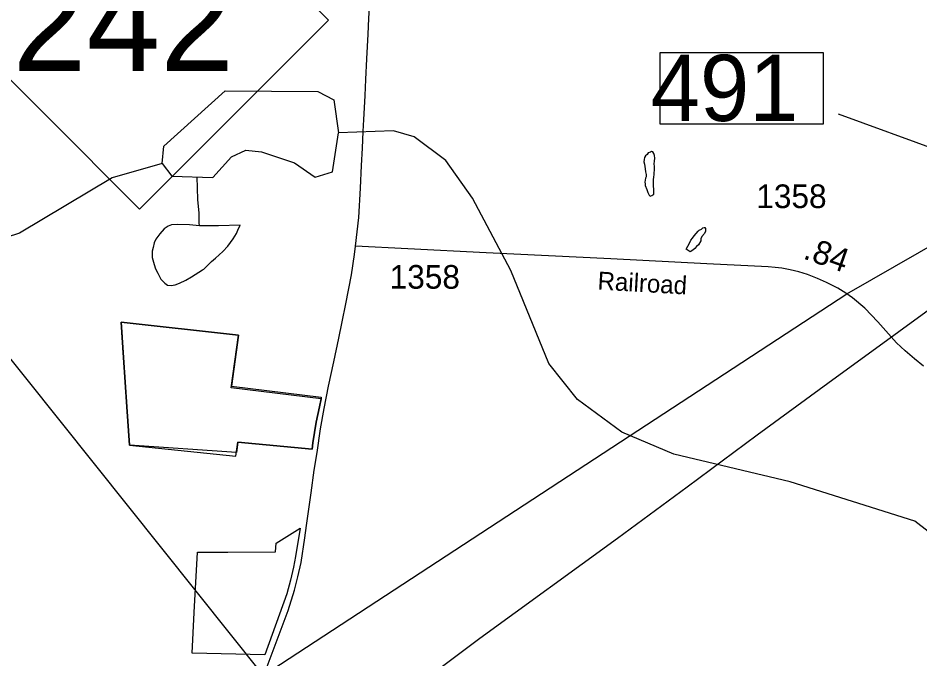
# Model space of a CAD drawing. Extents: x 2082433 to 2279600, y 546599 to 755198.
# Drawn here: x 2135079 to 2139852, y 600726 to 604115 of the extents above; entities that cross this region are included whole.
import ezdxf

# ---------------------------------------------------------------- set-up
doc = ezdxf.new("R2010")
doc.units = 0
for name, color, linetype in [('Exist Boundary Political City Limit New', 7, 'Continuous'), ('Exist Boundary Political Fire Districts', 7, 'Continuous'), ('Exist Hydrographic Misc Water Feature', 7, 'Continuous'), ('Exist Hydrographic Pond Under 1500 Sq Ft', 7, 'Continuous'), ('Exist Road Primary Interstate Structure Standard Bridge Number Label', 7, 'Continuous'), ('Exist Road Primary NC Attributed', 7, 'Continuous'), ('Exist Road Primary NC Shield CELL', 7, 'Continuous'), ('Exist Road Primary NC Shield Number Label', 7, 'Continuous'), ('Exist Road Secondary Mileage Hundredths English Label', 7, 'Continuous'), ('Exist Road Secondary Type 51 Attributed', 7, 'Continuous'), ('Exist Road Secondary Type 51 Label', 7, 'Continuous'), ('Exist Road Secondary Type 51 Number Label', 7, 'Continuous'), ('Exist Utilities Electrical Transmission Line', 7, 'Continuous'), ('Map Preparation Boundary City Limit Buffer Line', 7, 'Continuous')]:
    doc.layers.add(name, color=color, linetype=linetype)

msp = doc.modelspace()

# ---------------------------------------------------------------- linework, layer by layer
at = {"layer": 'Exist Boundary Political City Limit New'}
for points in [[(2136656.5, 601978.1), (2136639.5, 601868.3), (2136635, 601835.1), (2136242.8, 601872.6), (2136234.8, 601817.2), (2135669.8, 601856.6), (2135655.8, 602058.8), (2135637.5, 602320.6), (2135635.8, 602344.6), (2135624.5, 602506.8), (2136245.8, 602438.5), (2136208.8, 602168.7), (2136684.2, 602110.8), (2136682.5, 602101.9), (2136673.8, 602058.5), (2136656.5, 601978.1)], [(2136502.5, 601071.1), (2136385, 600748.5), (2136000, 600756.9), (2136012, 600970.8), (2136028.8, 601290.8), (2136036, 601290.8), (2136188.8, 601291.4), (2136442.5, 601292.2), (2136445.8, 601338.6), (2136573, 601417.9), (2136548, 601268.2), (2136536.8, 601211.1), (2136520.8, 601142.6), (2136502.5, 601071.1)]]:
    msp.add_lwpolyline(points, dxfattribs=at)
at = {"layer": 'Exist Boundary Political Fire Districts'}
for points in [[(2125185.8, 609236.3), (2127409.2, 608956.3), (2130289.8, 608255.9), (2136376.8, 600637.7), (2139465.5, 602656.7), (2141242.8, 603675.4), (2141795.1, 603915), (2144979.3, 603672.9), (2148226.1, 607636.4), (2150227.4, 608573.5)], [(2135669.7, 601856.6), (2136232, 601798.8), (2136242.7, 601872.6), (2136634.9, 601835), (2136639.4, 601868.3), (2136656.4, 601978.1), (2136673.7, 602058.5), (2136682.5, 602101.9), (2136207.6, 602159.7), (2136245.7, 602438.5), (2135624.4, 602506.7), (2135637.5, 602320.6), (2135655.8, 602058.8), (2135669.7, 601856.6)]]:
    msp.add_lwpolyline(points, dxfattribs=at)
at = {"layer": 'Exist Hydrographic Misc Water Feature'}
for points in [[(2140618.9, 600976.4), (2140058.9, 601273.1), (2139824.9, 601455.1), (2139165.9, 601661.9), (2138548.8, 601808.9), (2138273.9, 601926), (2138039.7, 602098.1), (2137888.8, 602288.1), (2137686.8, 602781), (2137484.8, 603162.3), (2137342.7, 603362), (2137175.8, 603486.7), (2137066.7, 603518.5), (2136775.7, 603508)], [(2135842.7, 603346.4), (2135576.8, 603269.9), (2135086.7, 602978), (2134878.8, 602910), (2134561.8, 602906.5), (2134136.7, 602980.7), (2133911.7, 602945.9), (2133803.7, 602912.1), (2133588.6, 602562.1), (2133447.7, 602496), (2133222.5, 602467.8), (2133089.7, 602509.9), (2132829.7, 602718.6), (2132636.7, 603089.9), (2132535.6, 603308.5), (2132318.7, 603473.6)], [(2138446.3, 603312.2), (2138448, 603330.2), (2138445.7, 603344), (2138447.6, 603358.3), (2138449.8, 603374.1), (2138448, 603388.2), (2138444.1, 603398.1), (2138437.5, 603408), (2138431.6, 603410.1), (2138425.8, 603406.2), (2138413.5, 603401.9), (2138407.6, 603393.9), (2138399.8, 603385.7), (2138393.9, 603377.8), (2138391.8, 603367.9), (2138391.6, 603354.1), (2138393.9, 603342), (2138398.4, 603317.8), (2138400, 603302.2), (2138402.3, 603288), (2138402.5, 603275.8), (2138400.2, 603268.1), (2138398.6, 603257.8), (2138396.5, 603248), (2138398.2, 603238), (2138398.6, 603229.8), (2138406.4, 603207.9), (2138412.7, 603192), (2138418.9, 603178.1), (2138425, 603173.9), (2138432.6, 603176), (2138438.8, 603180.3), (2138442.9, 603184.2), (2138444.5, 603202.2), (2138442.2, 603234.2), (2138442.5, 603248.3), (2138442.2, 603262.2), (2138444.1, 603274), (2138446.1, 603288.3), (2138446.1, 603294), (2138446.3, 603312.2)], [(2136039.9, 603015.6), (2136038, 603031.7), (2136038, 603055.6), (2136037.6, 603083.6), (2136031.4, 603155.5), (2136027.1, 603275.4)], [(2136039.9, 603015.6), (2135985.9, 603021.3), (2135922.2, 603023.2), (2135892, 603020.9), (2135874.4, 603015), (2135852.2, 603001), (2135830.3, 602974.7), (2135808.8, 602946.7), (2135800.6, 602926.4), (2135795, 602902.5), (2135789.1, 602882.3), (2135788.9, 602848.7), (2135799.1, 602812.7), (2135807.5, 602788.7), (2135819, 602766.7), (2135827.2, 602748.9), (2135835.4, 602735), (2135855.5, 602712.9), (2135869.7, 602703.1), (2135889.8, 602700.9), (2135911.7, 602705.2), (2135933.4, 602713.3), (2135967.5, 602729.2), (2135997.4, 602747.4), (2136054.8, 602783.8), (2136063.2, 602787.8), (2136087.2, 602812.1), (2136103, 602828), (2136124.7, 602846.2), (2136162.7, 602880.2), (2136190.4, 602908.4), (2136218.3, 602948.4), (2136236.1, 602976.6), (2136242.2, 602992.7), (2136254.1, 603020.4), (2136140.3, 603016.2), (2136058.1, 603015.6), (2136039.9, 603015.6)], [(2138691.6, 602937.3), (2138679.9, 602915.2), (2138670.1, 602907.3), (2138659.8, 602897.1), (2138649.6, 602887.3), (2138636, 602879.2), (2138626, 602885.2), (2138614.1, 602893.1), (2138631.7, 602925.3), (2138639.5, 602941.1), (2138647.5, 602951.2), (2138657.6, 602963.1), (2138667.8, 602975.4), (2138677.4, 602987.3), (2138683.4, 602993.3), (2138695.1, 602999.2), (2138703.3, 603005.3), (2138709.2, 603007.6), (2138713.5, 603007.4), (2138717.6, 603001.5), (2138717.4, 602987.3), (2138711.5, 602975.2), (2138697.3, 602959.5), (2138691.6, 602947.4), (2138691.6, 602937.3)]]:
    msp.add_lwpolyline(points, dxfattribs=at)
at = {"layer": 'Exist Hydrographic Pond Under 1500 Sq Ft'}
for points in [[(2135842.7, 603346.4), (2135850.7, 603438.1), (2136174.7, 603730.1), (2136665.8, 603726.7), (2136749.7, 603682.4), (2136775.7, 603508)], [(2136284.8, 603416.2), (2136367.7, 603408), (2136542.8, 603348.7), (2136651.7, 603274.3), (2136742.7, 603302), (2136775.7, 603508)], [(2135842.7, 603346.4), (2135892.8, 603279.8), (2136109.7, 603272.2), (2136209.8, 603381.7), (2136284.8, 603416.2)]]:
    msp.add_lwpolyline(points, dxfattribs=at)
at = {"layer": 'Exist Road Primary Interstate Structure Standard Bridge Number Label'}
msp.add_line((2141689.2, 602780.9), (2139421.4, 603606.5), dxfattribs=at)
msp.add_lwpolyline([(2139341.5, 603930.6), (2138475, 603930.6), (2138475, 603555), (2139341.5, 603555)], close=True, dxfattribs=at)
at = {"layer": 'Exist Road Primary NC Attributed'}
for points in [[(2136865.7, 602908), (2136882.2, 603060.7), (2136892.2, 603214.9), (2136897.5, 603335.6), (2136902.5, 603426.7), (2136906.2, 603515.6), (2136909, 603578.2), (2136910.3, 603609.2), (2136915.6, 603705.3), (2136920.6, 603789.5), (2136925.8, 603899.8), (2136932.1, 604030.3), (2136936.1, 604113.5), (2136942.3, 604235.4)], [(2136387.6, 600658.5), (2136508.9, 600982.1), (2136542.5, 601089.1), (2136559.9, 601160.1), (2136577.5, 601236.8), (2136597.1, 601367.2), (2136606.4, 601432.4), (2136630.1, 601605), (2136645.6, 601724.1), (2136661.8, 601818), (2136680.4, 601942.3), (2136699.7, 602049.9), (2136722.7, 602169.3), (2136750.1, 602297.1), (2136776.5, 602423), (2136794.9, 602508.2), (2136814.1, 602603.3), (2136843.7, 602757.8), (2136860.2, 602865.3), (2136865.7, 602908)]]:
    msp.add_lwpolyline(points, dxfattribs=at)
at = {"layer": 'Exist Road Primary NC Shield CELL'}
msp.add_lwpolyline([(2134723.7, 604103.5), (2135722.6, 605102.5), (2136721.6, 604103.5), (2135722.6, 603104.5)], close=True, dxfattribs=at)
at = {"layer": 'Exist Road Secondary Type 51 Attributed'}
msp.add_lwpolyline([(2139871, 602274.6), (2139822.4, 602312.3), (2139773.8, 602354.6), (2139728.1, 602398.1), (2139629.5, 602508.4), (2139560.2, 602581.8), (2139495.5, 602635.7), (2139459.3, 602661.1), (2139416.7, 602687.1), (2139358.1, 602717), (2139310.5, 602737.8), (2139256.1, 602758.9), (2139210.6, 602772.7), (2139164.5, 602784), (2139121.7, 602791.6), (2139085.7, 602796.4), (2139048.8, 602799.8), (2138724.8, 602815.8), (2138216.9, 602841.9), (2137556.8, 602873), (2137141.1, 602895.3), (2136865.7, 602908)], dxfattribs=at)
at = {"layer": 'Exist Utilities Electrical Transmission Line'}
msp.add_lwpolyline([(2135510.3, 599346), (2136050.3, 599742.2), (2136793.7, 600289.3), (2137523.2, 600836.5), (2138250.6, 601365.5), (2138619.3, 601637), (2138990, 601910.6), (2139364.7, 602184), (2139739.4, 602457.6), (2140486.9, 603000.7), (2140829.8, 603250.2), (2141575.1, 603803.2), (2141969.6, 604095), (2142338.3, 604368.5), (2142712.9, 604640), (2143476.4, 605209.1), (2143859, 605478.7), (2144235.8, 605746.2), (2144606.6, 606003.9), (2144985.1, 606269.4), (2145363.9, 606534.9), (2145742.6, 606790.6), (2146119.5, 607050.1), (2146496.2, 607313.6)], dxfattribs=at)
at = {"layer": 'Map Preparation Boundary City Limit Buffer Line'}
for points in [[(2136656.5, 601978.1), (2136639.5, 601868.3), (2136635, 601835.1), (2136242.8, 601872.6), (2136234.8, 601817.2), (2135669.8, 601856.6), (2135655.8, 602058.8), (2135637.5, 602320.6), (2135635.8, 602344.6), (2135624.5, 602506.8), (2136245.8, 602438.5), (2136208.8, 602168.7), (2136684.2, 602110.8), (2136682.5, 602101.9), (2136673.8, 602058.5), (2136656.5, 601978.1)], [(2136502.5, 601071.1), (2136385, 600748.5), (2136000, 600756.9), (2136012, 600970.8), (2136028.8, 601290.8), (2136036, 601290.8), (2136188.8, 601291.4), (2136442.5, 601292.2), (2136445.8, 601338.6), (2136573, 601417.9), (2136548, 601268.2), (2136536.8, 601211.1), (2136520.8, 601142.6), (2136502.5, 601071.1)]]:
    msp.add_lwpolyline(points, dxfattribs=at)

# ---------------------------------------------------------------- texts
at = {"layer": 'Exist Road Primary Interstate Structure Standard Bridge Number Label'}
msp.add_text('491', height=350, dxfattribs=at).set_placement((2138427.6, 603570.6))
at = {"layer": 'Exist Road Primary NC Shield Number Label'}
msp.add_text('242', height=525, dxfattribs=at).set_placement((2135051, 603834.3))
at = {"layer": 'Exist Road Secondary Mileage Hundredths English Label'}
msp.add_text('.84', height=125, rotation=340.71, dxfattribs=at).set_placement((2139228.6, 602844.7))
at = {"layer": 'Exist Road Secondary Type 51 Label'}
msp.add_text('Railroad', height=95, rotation=356.7894, dxfattribs=at).set_placement((2138144.2, 602679.8))
at = {"layer": 'Exist Road Secondary Type 51 Number Label'}
for p in [(2138985.9, 603110.2), (2137045.9, 602683.9)]:
    msp.add_text('1358', height=125, dxfattribs=at).set_placement(p)

doc.saveas('drawing.dxf')
